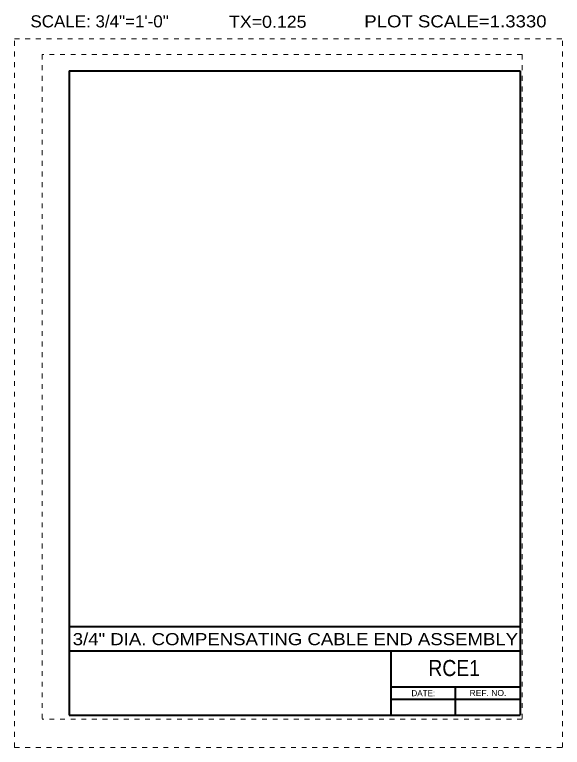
# Model space of a CAD drawing. Extents: x 1370 to 1381.3, y -905.5 to -890.3.
import ezdxf
from ezdxf.enums import TextEntityAlignment as Align

# ---------------------------------------------------------------- set-up
doc = ezdxf.new("R2010")
doc.units = 0
doc.header["$LTSCALE"] = 0.1
doc.linetypes.add('DOTTED', pattern=[1.5, 0.3, -1.2])
for name, color, linetype in [('57', 7, 'Continuous'), ('58', 7, 'Continuous'), ('59', 7, 'Continuous'), ('9', 7, 'Continuous')]:
    doc.layers.add(name, color=color, linetype=linetype)
for name, color, linetype, lineweight in [('61', 7, 'DOTTED', 13), ('62', 7, 'DOTTED', 13), ('63', 7, 'Continuous', 40)]:
    doc.layers.add(name, color=color, linetype=linetype, lineweight=lineweight)

msp = doc.modelspace()

# ---------------------------------------------------------------- linework, layer by layer
at = {"layer": '61'}
for p, q in [((1380.5162, -891.1754), (1370.5824, -891.1754)), ((1370.5824, -891.1754), (1370.5824, -904.9321)), ((1380.5162, -891.1754), (1380.5162, -904.9321)), ((1380.5162, -904.9321), (1370.5824, -904.9321))]:
    msp.add_line(p, q, dxfattribs=at)
at = {"layer": '62'}
for p, q in [((1370.0158, -905.5121), (1370.0158, -890.8454)), ((1370.0158, -890.8454), (1381.3496, -890.8454)), ((1381.3496, -905.5121), (1381.3496, -890.8454)), ((1370.0158, -905.5121), (1381.3496, -905.5121))]:
    msp.add_line(p, q, dxfattribs=at)
at = {"layer": '63'}
for p, q in [((1371.1408, -891.5121), (1371.1408, -904.8454)), ((1371.1408, -891.5121), (1380.4746, -891.5121)), ((1380.4746, -891.5121), (1380.4746, -904.8454)), ((1371.1408, -903.0121), (1380.4746, -903.0121)), ((1371.1408, -903.5121), (1380.4746, -903.5121)), ((1377.8077, -904.8454), (1377.8077, -903.5121)), ((1377.8077, -904.2621), (1380.4746, -904.2621)), ((1379.1412, -904.8454), (1379.1412, -904.2621)), ((1377.8077, -904.5121), (1380.4746, -904.5121)), ((1371.1408, -904.8454), (1380.4746, -904.8454))]:
    msp.add_line(p, q, dxfattribs=at)

# ---------------------------------------------------------------- texts
at = {"layer": '57', "width": 1.15}
msp.add_text('3/4" DIA. COMPENSATING CABLE END ASSEMBLY', height=0.25, dxfattribs=at).set_placement((1375.8255, -903.3976), align=Align.CENTER)
at = {"layer": '58', "width": 0.9}
msp.add_text('RCE1', height=0.3333, dxfattribs=at).set_placement((1379.111, -904.0374), align=Align.CENTER)
at = {"layer": '59'}
msp.add_text('DATE:', height=0.1251, dxfattribs=at).set_placement((1378.4729, -904.4534), align=Align.CENTER)
at = {"layer": '59', "width": 1.05}
msp.add_text('REF. NO.', height=0.1252, dxfattribs=at).set_placement((1379.8106, -904.4491), align=Align.CENTER)
at = {"layer": '9'}
for s, width, p in [('SCALE: 3/4"=1\'-0"', 1.05, (1371.7732, -890.6112)), ('TX=0.125', 1.1, (1375.2533, -890.6194)), ('PLOT SCALE=1.3330', 1.15, (1379.137, -890.6112))]:
    msp.add_text(s, height=0.25, dxfattribs=dict(at, width=width)).set_placement(p, align=Align.CENTER)

doc.saveas('drawing.dxf')
